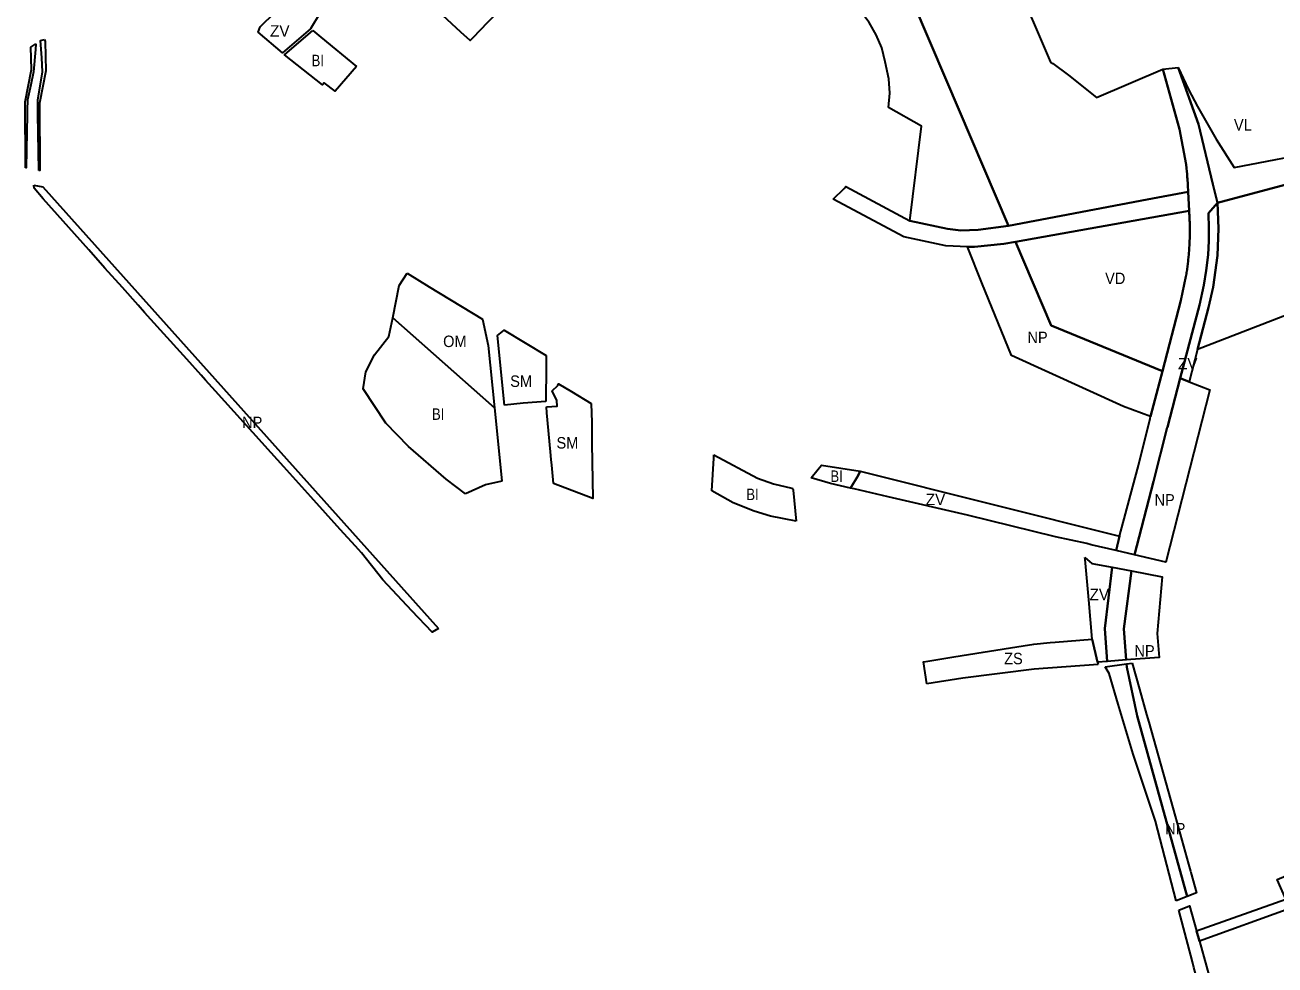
# Model space of a CAD drawing. Extents: x -650971 to -642489, y -1074311 to -1062745.
# Drawn here: x -650276 to -648968, y -1070700 to -1069716 of the extents above; entities that cross this region are included whole.
import ezdxf

# ---------------------------------------------------------------- set-up
doc = ezdxf.new("R2010")
doc.units = 0
doc.header["$LTSCALE"] = 4.8
for name, color, linetype, lineweight in [('12', 7, 'Continuous', 35), ('13', 7, 'Continuous', 35), ('15', 7, 'Continuous', 35), ('18', 7, 'Continuous', 35), ('2', 7, 'Continuous', 35), ('24', 7, 'Continuous', 35), ('35', 7, 'Continuous', 35), ('40', 7, 'Continuous', 35), ('41', 7, 'Continuous', 35), ('48', 7, 'Continuous', 35), ('62', 7, 'Continuous', 35)]:
    doc.layers.add(name, color=color, linetype=linetype, lineweight=lineweight)

msp = doc.modelspace()

# ---------------------------------------------------------------- linework, layer by layer
at = {"layer": '12'}
for points in [[(-649891.21, -1070022.68), (-649884.59, -1069988.57), (-649876.31, -1069975.93)], [(-649876.31, -1069975.93), (-649853.14, -1069989.98), (-649797.45, -1070023.77), (-649791.31, -1070051.51), (-649784.87, -1070116.76), (-649891.21, -1070022.68)]]:
    msp.add_lwpolyline(points, dxfattribs=at)
at = {"layer": '13'}
for points in [[(-649048.918, -1070055.852), (-649037.411, -1070011.659), (-649032.644, -1069990.371), (-649028.007, -1069957.455), (-649027.135, -1069928.902), (-649028.017, -1069902.109), (-648800.85, -1069841.52)], [(-648502.048, -1069957.969), (-648533.79, -1069913.49), (-648562.242, -1069870.301), (-648767.83, -1069946.87), (-648799.32, -1069959.08), (-648855.72, -1069980.96), (-648878.623, -1069989.839), (-648896.48, -1069996.77), (-649048.918, -1070055.852)]]:
    msp.add_lwpolyline(points, dxfattribs=at)
at = {"layer": '15'}
for points in [[(-649069.4, -1069760.67), (-649058.34, -1069783.72), (-649049.22, -1069801.23), (-649029.61, -1069835.47), (-649010.55, -1069865.09), (-648916.03, -1069847.12), (-648846.934, -1069832.583), (-648806.946, -1069821.79), (-648800.85, -1069841.52), (-649028.017, -1069902.109)], [(-649028.017, -1069902.109), (-649032.928, -1069882.782), (-649048, -1069820), (-649069.4, -1069760.67)], [(-649430.515, -1069898.514), (-649418.94, -1069887.36), (-649417.234, -1069885.193), (-649350.222, -1069920.873)], [(-649246.81, -1069926.27), (-649101.89, -1069898.73), (-649058.82, -1069890.548), (-649057.868, -1069910.51), (-649239.635, -1069943.094)], [(-649289.95, -1069948.146), (-649312.646, -1069947.342), (-649356.458, -1069937.945), (-649430.515, -1069898.514)], [(-649350.222, -1069920.873), (-649310.738, -1069929.342), (-649296.851, -1069931.092), (-649278.492, -1069930.573), (-649246.81, -1069926.27)], [(-649239.635, -1069943.094), (-649251.805, -1069945.276), (-649282.437, -1069948.342), (-649289.95, -1069948.146)]]:
    msp.add_lwpolyline(points, dxfattribs=at)
at = {"layer": '18'}
for points in [[(-649774.45, -1070113.92), (-649781.53, -1070041.2), (-649774.73, -1070035.58), (-649730.6, -1070061.98)], [(-649730.6, -1070061.98), (-649730.89, -1070088.96), (-649730.96, -1070094.91), (-649731.12, -1070109.96)], [(-649730.57, -1070115.76), (-649719.24, -1070114.87), (-649719.69, -1070108.94), (-649724.36, -1070099.03), (-649718.71, -1070093.35), (-649717.72, -1070091.61), (-649704.42, -1070099.48), (-649683.57, -1070112.05)], [(-649731.12, -1070109.96), (-649754.82, -1070111.89), (-649774.45, -1070113.92)], [(-649723.17, -1070195.81), (-649724.92, -1070176.78), (-649725.49, -1070170.64), (-649726.22, -1070162.75), (-649730, -1070122.01), (-649730.57, -1070115.76)], [(-649683.57, -1070112.05), (-649682.98, -1070132.1), (-649683.09, -1070148.44), (-649683.12, -1070154.14)], [(-649683.12, -1070154.14), (-649682.04, -1070211.58), (-649723.17, -1070195.81)]]:
    msp.add_lwpolyline(points, dxfattribs=at)
at = {"layer": '2'}
msp.add_line((-649891.21, -1070022.68), (-649784.87, -1070116.76), dxfattribs=at)
for points in [[(-649808.96, -1069675.34), (-649777.94, -1069699.2), (-649792.13, -1069713.65), (-649807.66, -1069729.46), (-649810.41, -1069732.28), (-649819.9, -1069723.61), (-649838.99, -1069706.15)], [(-649929.38, -1069759.65), (-649951.56, -1069785.42), (-649963, -1069776.7), (-649965, -1069778.7), (-650004.59, -1069747.27), (-649974.86, -1069721.96)], [(-649974.86, -1069721.96), (-649966.52, -1069728.87), (-649929.38, -1069759.65)], [(-649815.33, -1070206.63), (-649835.28, -1070191.27), (-649874.94, -1070157.19), (-649898.55, -1070132.9), (-649922.3, -1070096.9), (-649919.55, -1070079.01), (-649910.34, -1070061.29), (-649895.45, -1070042.15), (-649891.21, -1070022.68)], [(-649784.87, -1070116.76), (-649779.75, -1070168.69), (-649777.29, -1070193.57)], [(-649557.21, -1070203.53), (-649555.15, -1070169.51), (-649555.44, -1070165.91)], [(-649555.44, -1070165.91), (-649509.72, -1070190.24), (-649492.67, -1070196.34), (-649473.64, -1070200.92), (-649472.6, -1070201.15)], [(-649453.27, -1070190.02), (-649446.19, -1070180.76), (-649442.63, -1070176.69), (-649402.29, -1070182.92)], [(-649777.29, -1070193.57), (-649794.37, -1070197.2), (-649815.33, -1070206.63)], [(-649412.2, -1070200.71), (-649433.3, -1070195.89), (-649453.27, -1070190.02)], [(-649402.29, -1070182.92), (-649404.2, -1070187.43), (-649412.2, -1070200.71)], [(-649469.176, -1070235.365), (-649496, -1070230), (-649513, -1070225), (-649535, -1070216), (-649557.21, -1070203.53)], [(-649472.6, -1070201.15), (-649472.43, -1070202.9), (-649469.176, -1070235.365)]]:
    msp.add_lwpolyline(points, dxfattribs=at)
at = {"layer": '24'}
for p, q in [((-649057.868, -1069910.51), (-649058.82, -1069890.548)), ((-649134.294, -1070266.095), (-649130.712, -1070250.935)), ((-649145.73, -1070387.91), (-649123.385, -1070384.775))]:
    msp.add_line(p, q, dxfattribs=at)
for points in [[(-649058.82, -1069890.548), (-649058.858, -1069889.759), (-649058.944, -1069888.057), (-649059.035, -1069886.355), (-649059.165, -1069884.085), (-649059.233, -1069882.951), (-649059.339, -1069881.25), (-649059.489, -1069878.982), (-649059.647, -1069876.714), (-649059.73, -1069875.581), (-649059.858, -1069873.881), (-649060.037, -1069871.615), (-649060.177, -1069869.916), (-649060.273, -1069868.784), (-649060.472, -1069866.52), (-649060.627, -1069864.822), (-649060.787, -1069863.125), (-649060.897, -1069861.994), (-649068, -1069825.147), (-649085.41, -1069762.44), (-649069.4, -1069760.67)], [(-649069.4, -1069760.67), (-649048, -1069820), (-649032.928, -1069882.782), (-649028.017, -1069902.109)], [(-649028.017, -1069902.109), (-649037.665, -1069912.977), (-649037.137, -1069928.996), (-649037.322, -1069942.129), (-649037.98, -1069956.626), (-649039.966, -1069973.035), (-649042.468, -1069988.477), (-649047.131, -1070009.304), (-649067.061, -1070085.844)], [(-649085.737, -1070078.201), (-649066.487, -1070004.267), (-649061.139, -1069979.254), (-649060.909, -1069977.857), (-649060.686, -1069976.47), (-649060.47, -1069975.082), (-649060.26, -1069973.692), (-649060.058, -1069972.3), (-649059.862, -1069970.908), (-649059.672, -1069969.514), (-649059.49, -1069968.119), (-649059.314, -1069966.723), (-649059.145, -1069965.326), (-649058.983, -1069963.928), (-649058.827, -1069962.528), (-649058.678, -1069961.128), (-649058.536, -1069959.727), (-649058.401, -1069958.325), (-649058.273, -1069956.922), (-649058.151, -1069955.519), (-649058.036, -1069954.115), (-649057.929, -1069952.71), (-649057.827, -1069951.304), (-649057.733, -1069949.898), (-649057.646, -1069948.492), (-649057.565, -1069947.085), (-649057.491, -1069945.678), (-649057.424, -1069944.27), (-649057.364, -1069942.862), (-649057.311, -1069941.454), (-649057.264, -1069940.045), (-649057.225, -1069938.637), (-649057.192, -1069937.228), (-649057.166, -1069935.819), (-649057.147, -1069934.411), (-649057.134, -1069932.861), (-649057.129, -1069931.593), (-649057.131, -1069930.133), (-649057.139, -1069928.763), (-649057.152, -1069927.573), (-649057.172, -1069926.209), (-649057.186, -1069925.452), (-649057.216, -1069924.122), (-649057.247, -1069922.948), (-649057.276, -1069921.96), (-649057.308, -1069920.999), (-649057.378, -1069919.174), (-649057.438, -1069917.805), (-649057.505, -1069916.436), (-649057.598, -1069914.716), (-649057.657, -1069913.7), (-649057.773, -1069911.877), (-649057.868, -1069910.51)], [(-649067.061, -1070085.844), (-649080.38, -1070136.996), (-649080.924, -1070137.409), (-649095.152, -1070193.731), (-649115.159, -1070270.568), (-649134.294, -1070266.095)], [(-649130.712, -1070250.935), (-649114.174, -1070189.816), (-649110.925, -1070177.113), (-649098.65, -1070127.795), (-649098.101, -1070125.688), (-649085.737, -1070078.201)], [(-649143.633, -1070382.123), (-649146.163, -1070347.543), (-649138.43, -1070283.6), (-649118.257, -1070287.455)], [(-649118.257, -1070287.455), (-649126.069, -1070348.097), (-649123.693, -1070380.572), (-649143.633, -1070382.123)], [(-649071.33, -1070632.6), (-649093.2, -1070549.1), (-649116.56, -1070479.19), (-649132.07, -1070426.81), (-649141.48, -1070394.84), (-649145.73, -1070387.91)], [(-649123.385, -1070384.775), (-649123.138, -1070388.16), (-649112.14, -1070439.152), (-649059.951, -1070628.223), (-649071.33, -1070632.6)], [(-649068.65, -1070642.23), (-649057.338, -1070637.689), (-649050.081, -1070663.981), (-649047.11, -1070674.743), (-649025.129, -1070754.377), (-649014.888, -1070782.994), (-649003.641, -1070809.566), (-648998.132, -1070821.723), (-648991.386, -1070835.954), (-648985.145, -1070848.538), (-648976.834, -1070864.527)], [(-649007.885, -1070848.153), (-649010.67, -1070838.5), (-649011.24, -1070836.79), (-649018.48, -1070815.18), (-649019.48, -1070812.18), (-649027.64, -1070787.8), (-649027.74, -1070787.51), (-649038.416, -1070755.66), (-649039.06, -1070753.72), (-649040.03, -1070750.06), (-649051.03, -1070708.74), (-649052.77, -1070702.25), (-649054.31, -1070696.44), (-649068.65, -1070642.23)]]:
    msp.add_lwpolyline(points, dxfattribs=at)
at = {"layer": '35'}
msp.add_line((-649239.635, -1069943.094), (-649057.868, -1069910.51), dxfattribs=at)
for points in [[(-649246.81, -1069926.27), (-649312.03, -1069773.33), (-649364.44, -1069650.55), (-649379.32, -1069615.71), (-649388.438, -1069594.296), (-649409.349, -1069544.532), (-649416.52, -1069525.68), (-649431.761, -1069486.57)], [(-649144.57, -1069624.6), (-649241.11, -1069665.9), (-649202.99, -1069754.99), (-649200.64, -1069756.53), (-649184.05, -1069768.45), (-649154.76, -1069792.11), (-649085.41, -1069762.44)], [(-649085.41, -1069762.44), (-649068, -1069825.147), (-649060.897, -1069861.994), (-649060.787, -1069863.125), (-649060.627, -1069864.822), (-649060.472, -1069866.52), (-649060.273, -1069868.784), (-649060.177, -1069869.916), (-649060.037, -1069871.615), (-649059.858, -1069873.881), (-649059.73, -1069875.581), (-649059.647, -1069876.714), (-649059.489, -1069878.982), (-649059.339, -1069881.25), (-649059.233, -1069882.951), (-649059.165, -1069884.085), (-649059.035, -1069886.355), (-649058.944, -1069888.057), (-649058.858, -1069889.759), (-649058.82, -1069890.548)], [(-649058.82, -1069890.548), (-649101.89, -1069898.73), (-649246.81, -1069926.27)], [(-649057.868, -1069910.51), (-649057.773, -1069911.877), (-649057.657, -1069913.7), (-649057.598, -1069914.716), (-649057.505, -1069916.436), (-649057.438, -1069917.805), (-649057.378, -1069919.174), (-649057.308, -1069920.999), (-649057.276, -1069921.96), (-649057.247, -1069922.948), (-649057.216, -1069924.122), (-649057.186, -1069925.452), (-649057.172, -1069926.209), (-649057.152, -1069927.573), (-649057.139, -1069928.763), (-649057.131, -1069930.133), (-649057.129, -1069931.593), (-649057.134, -1069932.861), (-649057.147, -1069934.411), (-649057.166, -1069935.819), (-649057.192, -1069937.228), (-649057.225, -1069938.637), (-649057.264, -1069940.045), (-649057.311, -1069941.454), (-649057.364, -1069942.862), (-649057.424, -1069944.27), (-649057.491, -1069945.678), (-649057.565, -1069947.085), (-649057.646, -1069948.492), (-649057.733, -1069949.898), (-649057.827, -1069951.304), (-649057.929, -1069952.71), (-649058.036, -1069954.115), (-649058.151, -1069955.519), (-649058.273, -1069956.922), (-649058.401, -1069958.325), (-649058.536, -1069959.727), (-649058.678, -1069961.128), (-649058.827, -1069962.528), (-649058.983, -1069963.928), (-649059.145, -1069965.326), (-649059.314, -1069966.723), (-649059.49, -1069968.119), (-649059.672, -1069969.514), (-649059.862, -1069970.908), (-649060.058, -1069972.3), (-649060.26, -1069973.692), (-649060.47, -1069975.082), (-649060.686, -1069976.47), (-649060.909, -1069977.857), (-649061.139, -1069979.254), (-649066.487, -1070004.267), (-649085.737, -1070078.201)], [(-649085.737, -1070078.201), (-649202.375, -1070030.469), (-649239.635, -1069943.094)]]:
    msp.add_lwpolyline(points, dxfattribs=at)
at = {"layer": '40'}
for points in [[(-649957.15, -1069650.76), (-649950.69, -1069652.54), (-649957.54, -1069673.5), (-649958.87, -1069677.59), (-649967.27, -1069703.29), (-649977.31, -1069720.05), (-650006.85, -1069745.3), (-650032.13, -1069723.75), (-650030.26, -1069717.96), (-650014.74, -1069702.9)], [(-649067.061, -1070085.844), (-649047.131, -1070009.304), (-649042.468, -1069988.477), (-649039.966, -1069973.035), (-649037.98, -1069956.626), (-649037.322, -1069942.129), (-649037.137, -1069928.996), (-649037.665, -1069912.977), (-649028.017, -1069902.109)], [(-649028.017, -1069902.109), (-649027.135, -1069928.902), (-649028.007, -1069957.455), (-649032.644, -1069990.371), (-649037.411, -1070011.659), (-649048.918, -1070055.852), (-649057.722, -1070089.665), (-649067.061, -1070085.844)], [(-649412.2, -1070200.71), (-649404.2, -1070187.43), (-649402.29, -1070182.92), (-649130.712, -1070250.935), (-649134.294, -1070266.095)], [(-649134.294, -1070266.095), (-649160.54, -1070259.96), (-649164.91, -1070258.55), (-649197.55, -1070251.65), (-649289.83, -1070229.16), (-649372.69, -1070209.74), (-649408.24, -1070201.62), (-649412.2, -1070200.71)], [(-649166.86, -1070273.48), (-649159.78, -1070279.52), (-649138.43, -1070283.6)], [(-649159.19, -1070358.82), (-649162.91, -1070317.47), (-649166.68, -1070275.52), (-649166.86, -1070273.48)], [(-649138.43, -1070283.6), (-649146.163, -1070347.543), (-649143.633, -1070382.123), (-649153.64, -1070382.9), (-649159.19, -1070358.82)]]:
    msp.add_lwpolyline(points, dxfattribs=at)
at = {"layer": '41'}
for points in [[(-649331.3, -1070381.69), (-649304.18, -1070377.35), (-649273.57, -1070372.44), (-649231.39, -1070365.69), (-649220.47, -1070363.94), (-649203.4, -1070362.23), (-649197.91, -1070361.8), (-649159.19, -1070358.82), (-649153.64, -1070382.9), (-649153.11, -1070385.21)], [(-649332.2, -1070405.42), (-649335.79, -1070382.41), (-649331.3, -1070381.69)], [(-649153.11, -1070385.21), (-649220.16, -1070390.26), (-649294.79, -1070399.65), (-649332.2, -1070405.42)]]:
    msp.add_lwpolyline(points, dxfattribs=at)
at = {"layer": '48'}
msp.add_line((-649123.385, -1070384.775), (-649117.36, -1070383.93), dxfattribs=at)
for points in [[(-649431.761, -1069486.57), (-649416.52, -1069525.68), (-649409.349, -1069544.532), (-649388.438, -1069594.296), (-649379.32, -1069615.71), (-649364.44, -1069650.55), (-649312.03, -1069773.33), (-649246.81, -1069926.27)], [(-649372.56, -1069802.33), (-649370.94, -1069787.45), (-649372.2, -1069772.58), (-649376.01, -1069754.58), (-649379.49, -1069740.04), (-649385.25, -1069726.48), (-649392.85, -1069713.53), (-649401.77, -1069701.47), (-649415.12, -1069685.26), (-649474.46, -1069613.59), (-649507.23, -1069573.85), (-649517.81, -1069563.27), (-649527.84, -1069552.16), (-649538.49, -1069541.54), (-649548.881, -1069530.963)], [(-650275.76, -1069865.474), (-650276.214, -1069796.532), (-650269.449, -1069762.714), (-650270.059, -1069739.232), (-650264.91, -1069735.69)], [(-650264.91, -1069735.69), (-650265.37, -1069741.61), (-650267.22, -1069765.1), (-650270.15, -1069778.65), (-650273.58, -1069794.48), (-650273.78, -1069805.2), (-650273.87, -1069809.74), (-650274.95, -1069865.62), (-650275.76, -1069865.474)], [(-650261.8, -1069868.33), (-650262.7, -1069809.89), (-650262.77, -1069805.54), (-650262.93, -1069794.84), (-650257.77, -1069765.2), (-650258.74, -1069750.62), (-650259.97, -1069732.29), (-650255.716, -1069731.162)], [(-650255.716, -1069731.162), (-650255.21, -1069733.253), (-650254.411, -1069764.006), (-650261.204, -1069797.969), (-650260.748, -1069867.327), (-650260.645, -1069868.536), (-650261.8, -1069868.33)], [(-649350.222, -1069920.873), (-649338, -1069822), (-649372.56, -1069802.33)], [(-650266.89, -1069883.7), (-650257.713, -1069885.547), (-649843.513, -1070347.685)], [(-649843.513, -1070347.685), (-649850.04, -1070351.64), (-649871.28, -1070329.01), (-649901.59, -1070296.73), (-649924.15, -1070268.55), (-649930.46, -1070261.54), (-649946.39, -1070243.87), (-649977.05, -1070209.85), (-650005.3, -1070178.51), (-650018.41, -1070163.97), (-650037.78, -1070142.48), (-650076.72, -1070099.29), (-650087.18, -1070087.68), (-650091.89, -1070082.46), (-650106.76, -1070065.96), (-650134.26, -1070035.45), (-650151.03, -1070016.84), (-650157.87, -1070009.26), (-650174.3, -1069990.86), (-650192.51, -1069970.47), (-650209.51, -1069951.43), (-650257.16, -1069898.07), (-650266.68, -1069886.78), (-650266.89, -1069883.7)], [(-649246.81, -1069926.27), (-649278.492, -1069930.573), (-649296.851, -1069931.092), (-649310.738, -1069929.342), (-649350.222, -1069920.873)], [(-649289.95, -1069948.146), (-649282.437, -1069948.342), (-649251.805, -1069945.276), (-649239.635, -1069943.094)], [(-649239.635, -1069943.094), (-649202.375, -1070030.469), (-649085.737, -1070078.201), (-649098.101, -1070125.688)], [(-649098.101, -1070125.688), (-649126.437, -1070115.217), (-649243.846, -1070062.071), (-649274.733, -1069985.749), (-649289.95, -1069948.146)], [(-649115.159, -1070270.568), (-649095.152, -1070193.731), (-649080.924, -1070137.409), (-649080.38, -1070136.996), (-649067.061, -1070085.844), (-649057.722, -1070089.665)], [(-649057.722, -1070089.665), (-649036.031, -1070097.854), (-649082.233, -1070278.265), (-649115.159, -1070270.568)], [(-649059.951, -1070628.223), (-649112.14, -1070439.152), (-649123.138, -1070388.16), (-649123.385, -1070384.775)], [(-649117.36, -1070383.93), (-649109.76, -1070411.05), (-649102.31, -1070437.61), (-649100.01, -1070445.82)], [(-649100.01, -1070445.82), (-649072.47, -1070544.09), (-649065.42, -1070569.21), (-649058.38, -1070594.33), (-649056.32, -1070601.67), (-649055.93, -1070603.08), (-649049.96, -1070624.38), (-649059.951, -1070628.223)], [(-649050.081, -1070663.981), (-648956.687, -1070630.825), (-648965.569, -1070610.382), (-648941.064, -1070599.735)], [(-649025.129, -1070754.377), (-648924.668, -1070712.022), (-648922.196, -1070710.207), (-648952.455, -1070640.564), (-649047.11, -1070674.743), (-649050.081, -1070663.981)]]:
    msp.add_lwpolyline(points, dxfattribs=at)
msp.add_lwpolyline([(-649123.693, -1070380.572), (-649126.069, -1070348.097), (-649118.257, -1070287.455), (-649086.157, -1070293.589), (-649091.46, -1070352.73), (-649089.07, -1070377.88)], close=True, dxfattribs=at)

# ---------------------------------------------------------------- texts
at = {"layer": '62'}
for p in [(-650019.82, -1069728.32), (-649069.527, -1070076.528), (-649333.527, -1070218.528), (-649162.076, -1070318.026)]:
    msp.add_text('ZV', height=12, dxfattribs=at).set_placement(p)
for s, width, p in [('BI', 0.85, (-649976.221, -1069759.292)), ('VL', 0.95, (-649010.928, -1069826.6)), ('VD', 0.95, (-649145.767, -1069987.204)), ('NP', 0.95, (-649227.076, -1070049.026)), ('OM', 0.95, (-649838.604, -1070053.132)), ('SM', 0.95, (-649768.411, -1070094.846)), ('NP', 0.95, (-650048.985, -1070137.967)), ('BI', 0.85, (-649850.221, -1070129.292)), ('SM', 0.95, (-649719.964, -1070159.337)), ('BI', 0.85, (-649433.221, -1070194.292)), ('BI', 0.85, (-649521.221, -1070213.292)), ('NP', 0.95, (-649094.076, -1070219.026)), ('ZS', 0.95, (-649251.482, -1070385.05)), ('NP', 0.95, (-649115.076, -1070377.026)), ('NP', 0.95, (-649082.942, -1070563.157))]:
    msp.add_text(s, height=12, dxfattribs=dict(at, width=width)).set_placement(p)

doc.saveas('drawing.dxf')
